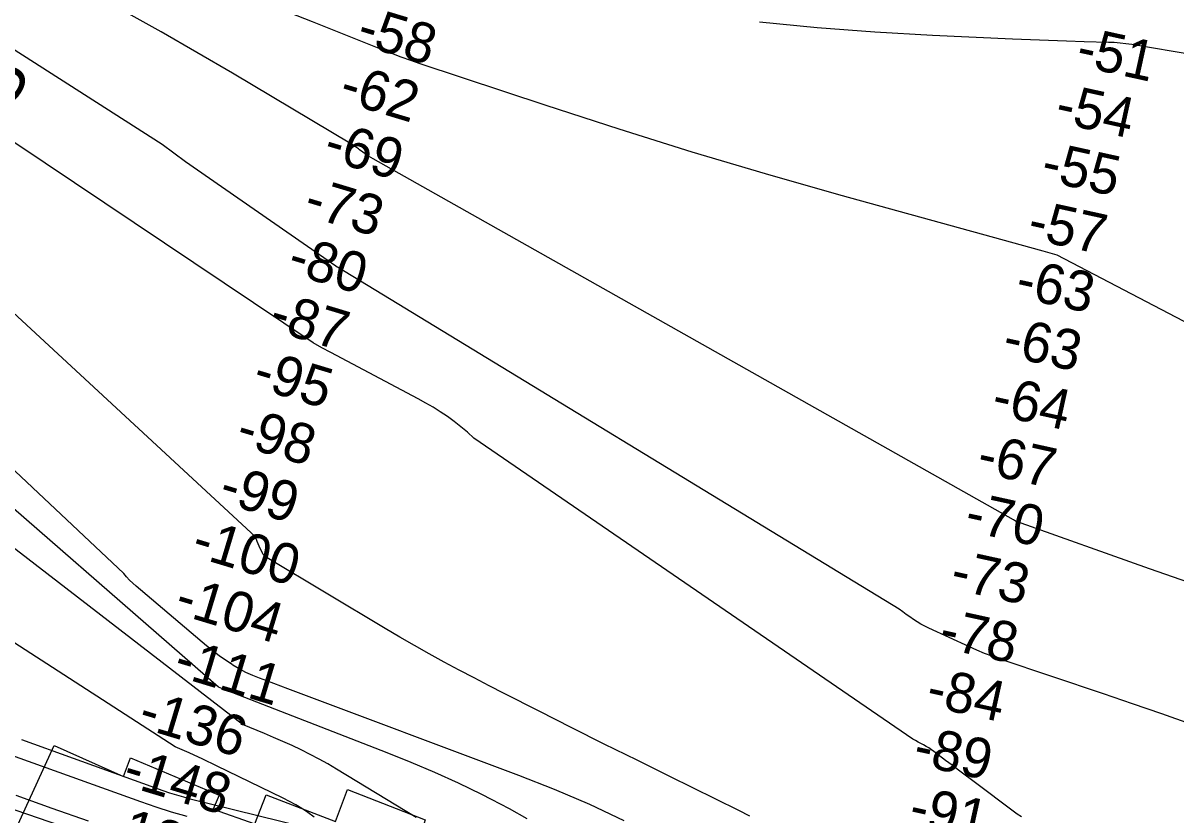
# Model space of a CAD drawing. Extents: x 3651524 to 3689615, y 505651 to 531377.
# Drawn here: x 3663757 to 3665685, y 514096 to 515421 of the extents above; entities that cross this region are included whole.
import ezdxf

# ---------------------------------------------------------------- set-up
doc = ezdxf.new("R2010")
doc.units = 0
for name, color, linetype in [('V-RIVR-RANG', 7, 'Continuous'), ('V-RRAP-RVMT', 7, 'Continuous'), ('V-TOPO-MAJR', 7, 'Continuous'), ('V-TOPO-MINR', 7, 'Continuous'), ('V-UTIL-IDEN', 7, 'Continuous')]:
    doc.layers.add(name, color=color, linetype=linetype)

msp = doc.modelspace()

# ---------------------------------------------------------------- linework, layer by layer
at = {"layer": 'V-RRAP-RVMT'}
for points in [[(3663733.24, 514046.983), (3663808.811, 514212.31), (3663924.63, 514160.672), (3663936.409, 514191.786), (3664084.597, 514129.561), (3664075.078, 514106.061), (3664144.558, 514081.389), (3664163.493, 514130.092)], [(3664163.493, 514130.092), (3664279.35, 514085.276), (3664299.689, 514138.573), (3664429.623, 514088.186), (3664427.728, 514082.488), (3664529.637, 514042.751), (3664536.084, 514059.024), (3664667.871, 514008.118), (3664671.207, 514016.256), (3664816.949, 513959.334), (3664813.864, 513950.433), (3664930.737, 513904.879), (3664933.268, 513911.451), (3665064.256, 513860.311), (3665065.998, 513864.998), (3665197.777, 513813.471), (3665198.66, 513816.567), (3665329.859, 513765.036), (3665335.569, 513780.162), (3665481.171, 513722.981), (3665478.365, 513715.311), (3665609.408, 513663.482), (3665552.051, 513515.327), (3665787.533, 513447.498)]]:
    msp.add_lwpolyline(points, dxfattribs=at)
at = {"layer": 'V-TOPO-MAJR'}
for points in [[(3664972.832, 514094.245), (3664954.357, 514103.469), (3664838.592, 514160.499), (3664783.86, 514187.582), (3664729.192, 514214.794), (3664674.621, 514242.2), (3664620.115, 514269.735), (3664561.823, 514299.313), (3664536.564, 514312.258), (3664511.377, 514325.34), (3664486.298, 514338.626), (3664461.29, 514352.048), (3664436.424, 514365.729), (3664411.677, 514379.617), (3664387.107, 514393.817), (3664362.656, 514408.225), (3664165.422, 514526.133), (3664164.335, 514526.807), (3664161.177, 514528.982), (3664159.374, 514530.716), (3664158.662, 514531.737), (3664158.045, 514532.835), (3664151.965, 514545.837), (3664148.69, 514553.595), (3664145.816, 514561.483), (3663221.235, 515416.741)], [(3665716.838, 515367.21), (3665611.615, 515384.97), (3665601.871, 515386.403), (3665592.1, 515387.558), (3665582.29, 515388.297), (3665572.452, 515388.758), (3665532.173, 515389.792), (3665502.179, 515390.646), (3665472.188, 515391.611), (3665442.204, 515392.746), (3665412.223, 515393.992), (3665278.412, 515399.931), (3665181.645, 515405.528), (3665085.031, 515412.851), (3664988.649, 515422.763)]]:
    msp.add_lwpolyline(points, dxfattribs=at)
at = {"layer": 'V-TOPO-MINR'}
for points in [[(3666395.039, 514558.226), (3665486.98, 515032.661), (3665463.567, 515039.229), (3665121.619, 515133.84), (3664998.581, 515168.901), (3664875.923, 515205.214), (3664753.837, 515243.405), (3664632.133, 515282.847), (3664421.275, 515352.975), (3664405.336, 515358.433), (3664389.465, 515364.076), (3664373.696, 515369.999), (3664357.995, 515376.107), (3664240.988, 515422.819), (3664166.735, 515452.164), (3664092.349, 515481.163), (3664017.762, 515509.645), (3663943.043, 515537.781), (3663413.207, 515735.196)], [(3665710.577, 514248.105), (3665661.818, 514265.157), (3665612.976, 514281.969), (3665564.079, 514298.621), (3665391.184, 514357.024), (3665378.192, 514361.646), (3665365.308, 514366.54), (3665352.587, 514371.843), (3665339.975, 514377.419), (3665271.861, 514408.842), (3665265.278, 514412.082), (3665258.815, 514415.535), (3665252.533, 514419.308), (3665246.373, 514423.294), (3665240.337, 514427.487), (3665234.346, 514431.743), (3665228.423, 514436.092), (3665222.545, 514440.503), (3664282.797, 515012.609), (3664282.403, 515012.807), (3664280.62, 515013.822), (3664280.199, 515014.11), (3664280.06, 515014.207), (3664279.92, 515014.304), (3664068.519, 515161.066), (3664048.569, 515175.034), (3664028.694, 515189.106), (3664008.931, 515203.335), (3663989.242, 515217.669), (3663349.816, 515627.266)], [(3665719.692, 514480.667), (3665641.138, 514508.188), (3665418.789, 514587.072), (3665418.092, 514587.321), (3665415.121, 514588.717), (3665413.604, 514589.706), (3664342.31, 515193.884), (3664338.356, 515196.127), (3664334.513, 515198.553), (3664330.743, 515201.102), (3664319.415, 515209.154), (3664317.759, 515210.342), (3664314.471, 515212.753), (3664311.195, 515215.176), (3664307.817, 515217.449), (3664306.084, 515218.52), (3664107.107, 515337.002), (3664047.582, 515371.911), (3663987.754, 515406.284), (3663927.472, 515439.856), (3663866.887, 515472.893), (3663848.363, 515482.834), (3663796.629, 515510.134), (3663744.648, 515536.948)], [(3665426.823, 514092.805), (3665420.028, 514097.765), (3665343.471, 514154.931), (3665332.631, 514163.04), (3665321.801, 514171.161), (3665310.984, 514179.3), (3665300.176, 514187.452), (3665280.428, 514202.373), (3665276.293, 514205.357), (3665272.076, 514208.215), (3665267.737, 514210.884), (3665263.318, 514213.428), (3665258.821, 514215.847), (3665254.304, 514218.226), (3665249.756, 514220.547), (3665245.188, 514222.828), (3664510.642, 514726.721), (3664500.143, 514736.335), (3664489.353, 514745.594), (3664478.127, 514754.319), (3664466.61, 514762.688), (3664454.746, 514770.576), (3664442.709, 514778.182), (3664430.415, 514785.364), (3664417.949, 514792.263), (3664271.722, 514869.902), (3664256.817, 514877.858), (3664241.936, 514885.856), (3663393.965, 515454.207)], [(3664176.26, 514315.935), (3664164.434, 514320.355), (3664152.607, 514324.771), (3664140.951, 514329.531), (3664129.521, 514334.75), (3664118.431, 514340.657), (3664107.568, 514347.022), (3664106.505, 514347.689), (3664095.449, 514354.965), (3664084.617, 514362.545), (3664074.121, 514370.584), (3664063.848, 514378.928), (3663946.039, 514478.887), (3663940.482, 514483.884), (3663935.129, 514489.078), (3663930.082, 514494.571), (3663925.24, 514500.263), (3663180.075, 515201.595)], [(3664600.208, 514089.656), (3664570.524, 514106.352), (3664540.345, 514122.21), (3664524.012, 514130.35), (3664485.052, 514149.102), (3664445.772, 514167.128), (3664406.009, 514184.064), (3664365.926, 514200.274), (3664097.501, 514304.545), (3664083.721, 514309.975), (3663154.429, 515119.701)], [(3664414.329, 514091.947), (3664281.237, 514172.968), (3664266.717, 514181.512), (3664252.037, 514189.76), (3664237.117, 514197.566), (3664222.037, 514205.077), (3664206.778, 514212.235), (3664191.442, 514219.218), (3664175.989, 514225.939), (3664160.458, 514232.486), (3664124.058, 514247.466), (3663109.74, 515029.767)], [(3664243.823, 514092.718), (3664233.085, 514100.161), (3664223.116, 514106.738), (3664212.963, 514113.002), (3664202.535, 514118.795), (3664191.922, 514124.274), (3664080.585, 514178.568), (3664057.702, 514189.469), (3664034.692, 514200.088), (3664011.492, 514210.283), (3663015.036, 514854.374)], [(3663404.705, 514315.396), (3663953.325, 514118.689), (3663978.989, 514109.923), (3664004.81, 514101.679), (3664030.869, 514094.219)], [(3664762.666, 514086.295), (3664704.677, 514113.604), (3664645.701, 514138.711), (3664586.068, 514162.351), (3664199.905, 514307.083), (3664188.083, 514311.511), (3664176.26, 514315.935)], [(3663754.168, 514222.699), (3663840.377, 514191.182), (3663990.495, 514137.357), (3664001.901, 514133.46), (3664013.377, 514129.796), (3664024.959, 514126.481), (3664036.611, 514123.397), (3664224.402, 514076.726)], [(3663578.724, 514160.815), (3663947.75, 514034.475)], [(3663744.491, 514129.046), (3663805.01, 514107.383), (3663865.769, 514086.374)]]:
    msp.add_lwpolyline(points, dxfattribs=at)

# ---------------------------------------------------------------- texts
at = {"layer": 'V-RIVR-RANG'}
for s, rotation, p in [('-58', 343.196917, (3664311.908, 515387.194)), ('-51', 347.616472, (3665515.783, 515350.535)), ('-62', 343.196917, (3664282.763, 515291.536)), ('-54', 347.616472, (3665480.698, 515255.856)), ('-69', 343.196917, (3664256.396, 515195.039)), ('-55', 347.616472, (3665457.208, 515158.632)), ('-73', 343.196917, (3664223.463, 515100.523)), ('-57', 347.616472, (3665434.49, 515061.239)), ('-80', 343.196917, (3664196.085, 515004.332)), ('-63', 347.616472, (3665414.349, 514963.279)), ('-87', 343.196917, (3664165.173, 514909.206)), ('-63', 347.616472, (3665392.662, 514865.659)), ('-95', 343.196917, (3664138.048, 514812.938)), ('-64', 347.616472, (3665374.326, 514767.304)), ('-98', 343.196917, (3664109.913, 514716.974)), ('-67', 347.616472, (3665349.805, 514670.305)), ('-99', 343.196917, (3664081.526, 514621.087)), ('-70', 347.616472, (3665329.406, 514572.402)), ('-100', 343.196917, (3664035.714, 514530.461)), ('-73', 347.616472, (3665305.4, 514475.291)), ('-104', 343.196917, (3664007.58, 514434.497)), ('-78', 347.616472, (3665286.289, 514377.106)), ('-111', 343.196917, (3664005.706, 514330.603)), ('-84', 347.616472, (3665264.86, 514279.429)), ('-136', 343.196917, (3663946.512, 514244.019)), ('-89', 347.616472, (3665243.173, 514181.809)), ('-148', 343.196917, (3663920.397, 514147.445)), ('-91', 347.616472, (3665235.914, 514081.021)), ('-126', 343.196917, (3663888.727, 514052.55))]:
    msp.add_text(s, height=67, rotation=rotation, dxfattribs=at).set_placement(p)
at = {"layer": 'V-UTIL-IDEN'}
msp.add_text('2-SUB CABLES', height=82.99983, rotation=56.946229, dxfattribs=at).set_placement((3663337.727, 514668.005))

doc.saveas('drawing.dxf')
